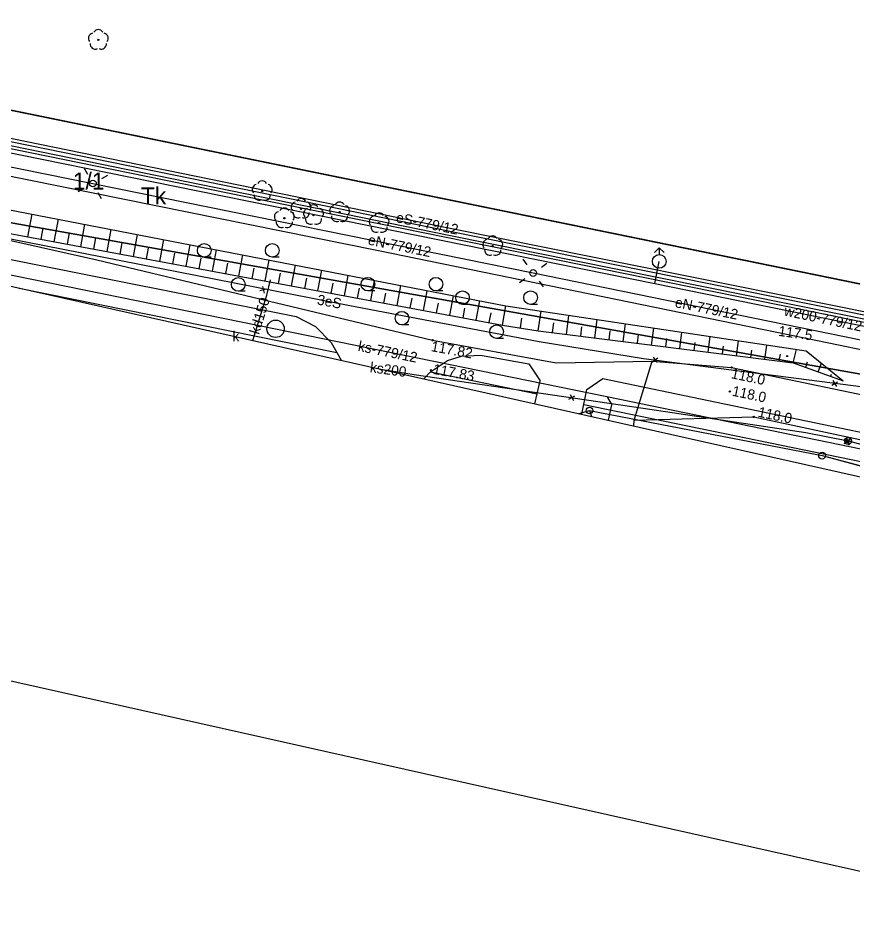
# Model space of a CAD drawing. Extents: x 6424617 to 6425697, y 5665845 to 5667190.
# Drawn here: x 6424720.9 to 6424782.2, y 5665988.5 to 5666054.9 of the extents above; entities that cross this region are included whole.
import ezdxf

# ---------------------------------------------------------------- set-up
doc = ezdxf.new("R2010")
doc.units = 0
for name, color, linetype in [('Warstwa 1', 7, 'Continuous'), ('Warstwa 10', 7, 'Continuous'), ('Warstwa 11', 7, 'Continuous'), ('Warstwa 12', 7, 'Continuous'), ('Warstwa 13', 7, 'Continuous'), ('Warstwa 14', 7, 'Continuous'), ('Warstwa 15', 7, 'Continuous'), ('Warstwa 2', 7, 'Continuous'), ('Warstwa 20', 7, 'Continuous'), ('Warstwa 21', 7, 'Continuous'), ('Warstwa 25', 7, 'Continuous'), ('Warstwa 4', 7, 'Continuous'), ('Warstwa 5', 7, 'Continuous'), ('Warstwa 6', 7, 'Continuous'), ('Warstwa 62', 7, 'Continuous'), ('Warstwa 63', 7, 'Continuous'), ('Warstwa 8', 7, 'Continuous')]:
    doc.layers.add(name, color=color, linetype=linetype)

msp = doc.modelspace()

# ---------------------------------------------------------------- linework, layer by layer
at = {"layer": 'Warstwa 1'}
for p, q in [((6424712.334, 5666049.725), (6424785.747, 5666034.716)), ((6424712.334, 5666049.725), (6424785.747, 5666034.716)), ((6424710.615, 5666041.565), (6424784.211, 5666028.454)), ((6424710.615, 5666041.565), (6424784.211, 5666028.454)), ((6424762.124, 5666025.803), (6424762.89, 5666026.032)), ((6424762.124, 5666025.803), (6424762.89, 5666026.032)), ((6424762.89, 5666026.032), (6424763.044, 5666025.596)), ((6424762.89, 5666026.032), (6424779.981, 5666022.715)), ((6424762.89, 5666026.032), (6424779.981, 5666022.715)), ((6424762.89, 5666026.032), (6424763.044, 5666025.596)), ((6424779.981, 5666022.715), (6424802.225, 5666016.812)), ((6424779.981, 5666022.715), (6424802.225, 5666016.812))]:
    msp.add_line(p, q, dxfattribs=at)
at = {"layer": 'Warstwa 10'}
for p, q in [((6424710.78, 5666042.623), (6424756.735, 5666033.713)), ((6424707.071, 5666041.492), (6424756.504, 5666032.304)), ((6424721.629, 5666038.786), (6424721.94, 5666040.458)), ((6424723.567, 5666038.426), (6424723.875, 5666040.084)), ((6424722.598, 5666038.606), (6424722.753, 5666039.438)), ((6424725.505, 5666038.065), (6424725.81, 5666039.708)), ((6424727.441, 5666037.706), (6424727.744, 5666039.334)), ((6424724.536, 5666038.245), (6424724.69, 5666039.071)), ((6424726.473, 5666037.885), (6424726.625, 5666038.704)), ((6424729.379, 5666037.345), (6424729.679, 5666038.959)), ((6424731.317, 5666036.985), (6424731.614, 5666038.583)), ((6424728.41, 5666037.526), (6424728.561, 5666038.336)), ((6424730.348, 5666037.165), (6424730.497, 5666037.968)), ((6424733.254, 5666036.625), (6424733.548, 5666038.209)), ((6424735.191, 5666036.265), (6424735.483, 5666037.833)), ((6424732.285, 5666036.805), (6424732.433, 5666037.6)), ((6424734.222, 5666036.445), (6424734.369, 5666037.233)), ((6424737.129, 5666035.904), (6424737.418, 5666037.458)), ((6424736.16, 5666036.084), (6424736.306, 5666036.865)), ((6424738.098, 5666035.725), (6424738.241, 5666036.498)), ((6424739.067, 5666035.545), (6424739.352, 5666037.082)), ((6424741.004, 5666035.184), (6424741.287, 5666036.708)), ((6424740.036, 5666035.365), (6424740.177, 5666036.129)), ((6424742.941, 5666034.824), (6424743.222, 5666036.333)), ((6424744.879, 5666034.464), (6424745.157, 5666035.957)), ((6424741.972, 5666035.004), (6424742.114, 5666035.762)), ((6424743.91, 5666034.644), (6424744.05, 5666035.394)), ((6424746.816, 5666034.104), (6424747.091, 5666035.583)), ((6424748.754, 5666033.744), (6424749.025, 5666035.207)), ((6424745.847, 5666034.285), (6424745.986, 5666035.027)), ((6424747.785, 5666033.924), (6424747.922, 5666034.66)), ((6424750.691, 5666033.384), (6424750.961, 5666034.833)), ((6424749.722, 5666033.564), (6424749.857, 5666034.292)), ((6424751.66, 5666033.204), (6424751.794, 5666033.925)), ((6424752.629, 5666033.024), (6424752.895, 5666034.457)), ((6424754.566, 5666032.664), (6424754.83, 5666034.082)), ((6424753.598, 5666032.844), (6424753.731, 5666033.557)), ((6424755.522, 5666032.487), (6424755.663, 5666033.194)), ((6424756.504, 5666032.304), (6424756.735, 5666033.713)), ((6424756.735, 5666033.713), (6424778.815, 5666030.409)), ((6424759.127, 5666031.882), (6424759.332, 5666033.325)), ((6424757.815, 5666032.093), (6424757.924, 5666032.806)), ((6424761.209, 5666031.622), (6424761.383, 5666033.018)), ((6424763.291, 5666031.362), (6424763.459, 5666032.707)), ((6424756.504, 5666032.304), (6424759.127, 5666031.882)), ((6424759.127, 5666031.882), (6424777.865, 5666029.538)), ((6424760.168, 5666031.751), (6424760.263, 5666032.461)), ((6424762.25, 5666031.492), (6424762.335, 5666032.177)), ((6424764.331, 5666031.231), (6424764.414, 5666031.891)), ((6424765.373, 5666031.1), (6424765.535, 5666032.396)), ((6424767.455, 5666030.84), (6424767.611, 5666032.085)), ((6424766.414, 5666030.97), (6424766.494, 5666031.606)), ((6424768.495, 5666030.711), (6424768.572, 5666031.32)), ((6424769.537, 5666030.58), (6424769.686, 5666031.775)), ((6424771.619, 5666030.32), (6424771.762, 5666031.464)), ((6424773.701, 5666030.059), (6424773.838, 5666031.153)), ((6424770.578, 5666030.449), (6424770.651, 5666031.035)), ((6424772.659, 5666030.189), (6424772.73, 5666030.749)), ((6424775.783, 5666029.798), (6424775.913, 5666030.843)), ((6424777.865, 5666029.538), (6424778.1, 5666030.515)), ((6424774.742, 5666029.929), (6424774.808, 5666030.463)), ((6424776.823, 5666029.668), (6424776.915, 5666030.174)), ((6424778.815, 5666030.409), (6424781.537, 5666028.2)), ((6424777.865, 5666029.538), (6424781.537, 5666028.2)), ((6424778.783, 5666029.204), (6424778.899, 5666029.607)), ((6424779.701, 5666028.869), (6424779.931, 5666029.503)), ((6424780.619, 5666028.534), (6424780.677, 5666028.693))]:
    msp.add_line(p, q, dxfattribs=at)
msp.add_lwpolyline([(6424656.071, 5666052.546), (6424661.157, 5666051.396), (6424669.018, 5666049.655), (6424675.606, 5666048.248), (6424687.507, 5666045.627), (6424688.596, 5666045.389), (6424711.614, 5666040.344), (6424745.27, 5666033.742), (6424759.201, 5666031.098), (6424766.854, 5666029.843), (6424786.263, 5666027.358), (6424788.423, 5666027.048), (6424792.547, 5666026.577), (6424800.463, 5666024.133), (6424809.296, 5666021.315), (6424821.58, 5666017.547), (6424829.542, 5666015.101), (6424836.576, 5666013.009), (6424850.417, 5666008.804), (6424857.534, 5666006.674), (6424862.301, 5666005.107)], dxfattribs=at)
for centre in [(6424762.89, 5666026.032), (6424779.981, 5666022.715)]:
    msp.add_circle(centre, 0.25, dxfattribs=at)
at = {"layer": 'Warstwa 11'}
for centre in [(6424726.8, 5666053.26), (6424738.84, 5666042.15), (6424741.7, 5666040.85), (6424742.61, 5666040.39), (6424744.53, 5666040.59), (6424740.47, 5666040.15), (6424747.43, 5666039.8), (6424755.78, 5666038.11)]:
    msp.add_circle(centre, 0.05, dxfattribs=at)
for centre, start, end in [((6424726.443, 5666053.376), 102.14713, 221.85287), ((6424726.8, 5666053.635), 30.14713, 149.85287), ((6424727.157, 5666053.376), 318.14713, 77.85287), ((6424726.58, 5666052.957), 174.14713, 293.85287), ((6424727.02, 5666052.957), 246.14713, 5.85287), ((6424738.483, 5666042.266), 102.14713, 221.85287), ((6424738.84, 5666042.525), 30.14713, 149.85287), ((6424739.197, 5666042.266), 318.14713, 77.85287), ((6424738.62, 5666041.847), 174.14713, 293.85287), ((6424739.06, 5666041.847), 246.14713, 5.85287), ((6424741.343, 5666040.966), 102.14713, 221.85287), ((6424741.7, 5666041.225), 30.14713, 149.85287), ((6424742.057, 5666040.966), 318.14713, 77.85287), ((6424742.61, 5666040.765), 30.14713, 149.85287), ((6424744.53, 5666040.965), 30.14713, 149.85287), ((6424740.113, 5666040.266), 102.14713, 221.85287), ((6424740.47, 5666040.525), 30.14713, 149.85287), ((6424740.827, 5666040.266), 318.14713, 77.85287), ((6424741.48, 5666040.547), 174.14713, 293.85287), ((6424741.92, 5666040.547), 246.14713, 5.85287), ((6424742.253, 5666040.506), 102.14713, 221.85287), ((6424742.967, 5666040.506), 318.14713, 77.85287), ((6424744.173, 5666040.706), 102.14713, 221.85287), ((6424744.887, 5666040.706), 318.14713, 77.85287), ((6424747.43, 5666040.175), 30.14713, 149.85287), ((6424740.25, 5666039.847), 174.14713, 293.85287), ((6424740.69, 5666039.847), 246.14713, 5.85287), ((6424742.39, 5666040.087), 174.14713, 293.85287), ((6424742.83, 5666040.087), 246.14713, 5.85287), ((6424744.31, 5666040.287), 174.14713, 293.85287), ((6424744.75, 5666040.287), 246.14713, 5.85287), ((6424747.073, 5666039.916), 102.14713, 221.85287), ((6424747.787, 5666039.916), 318.14713, 77.85287), ((6424747.21, 5666039.497), 174.14713, 293.85287), ((6424747.65, 5666039.497), 246.14713, 5.85287), ((6424755.423, 5666038.226), 102.14713, 221.85287), ((6424755.78, 5666038.485), 30.14713, 149.85287), ((6424756.137, 5666038.226), 318.14713, 77.85287), ((6424755.56, 5666037.807), 174.14713, 293.85287), ((6424756, 5666037.807), 246.14713, 5.85287)]:
    msp.add_arc(centre, 0.375, start, end, dxfattribs=at)
at = {"layer": 'Warstwa 12'}
for points in [[(6424738.156, 5666031.176), (6424739.178, 5666034.503), (6424739.443, 5666035.64)], [(6424747.564, 5666029.067), (6424750.011, 5666028.68), (6424766.827, 5666026.199), (6424778.788, 5666024.413), (6424781.89, 5666023.794), (6424800.356, 5666018.883), (6424811.076, 5666016.019), (6424822.07, 5666013.113), (6424829.403, 5666010.718)]]:
    msp.add_lwpolyline(points, dxfattribs=at)
at = {"layer": 'Warstwa 13'}
for centre in [(6424777.418, 5666030.032), (6424773.33, 5666029.19), (6424773.2, 5666027.42), (6424774.96, 5666025.56)]:
    msp.add_circle(centre, 0.045, dxfattribs=at)
at = {"layer": 'Warstwa 14'}
msp.add_circle((6424781.89, 5666023.794), 0.045, dxfattribs=at)
at = {"layer": 'Warstwa 20'}
for p, q in [((6424707.071, 5666041.492), (6424756.504, 5666032.304)), ((6424756.504, 5666032.304), (6424759.127, 5666031.882)), ((6424759.127, 5666031.882), (6424777.865, 5666029.538)), ((6424777.865, 5666029.538), (6424781.537, 5666028.2))]:
    msp.add_line(p, q, dxfattribs=at)
at = {"layer": 'Warstwa 21'}
for p, q in [((6424710.78, 5666042.623), (6424756.735, 5666033.713)), ((6424756.735, 5666033.713), (6424778.815, 5666030.409)), ((6424778.815, 5666030.409), (6424781.537, 5666028.2))]:
    msp.add_line(p, q, dxfattribs=at)
at = {"layer": 'Warstwa 25'}
for centre in [(6424751.36, 5666031.19), (6424751.23, 5666028.99)]:
    msp.add_circle(centre, 0.045, dxfattribs=at)
at = {"layer": 'Warstwa 4'}
msp.add_circle((6424781.89, 5666023.794), 0.25, dxfattribs=at)
at = {"layer": 'Warstwa 6'}
for p, q in [((6424735.08, 5666037.293), (6424734.58, 5666037.293)), ((6424740.08, 5666037.293), (6424739.58, 5666037.293)), ((6424737.58, 5666034.793), (6424737.08, 5666034.793)), ((6424747.11, 5666034.813), (6424746.61, 5666034.813)), ((6424752.11, 5666034.813), (6424751.61, 5666034.813)), ((6424754.06, 5666033.823), (6424753.56, 5666033.823)), ((6424759.06, 5666033.823), (6424758.56, 5666033.823)), ((6424749.61, 5666032.313), (6424749.11, 5666032.313)), ((6424756.56, 5666031.323), (6424756.06, 5666031.323))]:
    msp.add_line(p, q, dxfattribs=at)
for points in [[(6424658.972, 5666088.288), (6424687.905, 5666078.903), (6424716.673, 5666070.324), (6424715.697, 5666065.716), (6424712.334, 5666049.725), (6424785.747, 5666034.716), (6424788.428, 5666045.534), (6424790.341, 5666053.242), (6424828.327, 5666041.072), (6424860.534, 5666028.943), (6424934.12, 5666007.202), (6424963.728, 5665998.454), (6425016.619, 5665983.165), (6425073.513, 5665966.428), (6425123.829, 5665952.421), (6425122.41, 5665946.75), (6425151.645, 5665938.47)], [(6425042.513, 5665962.938), (6424959.921, 5665983.009), (6424856.845, 5666006.746), (6424825.409, 5666018.086), (6424784.685, 5666030.409), (6424784.211, 5666028.454), (6424710.615, 5666041.565), (6424651.301, 5666054.074)], [(6424762.124, 5666025.803), (6424762.89, 5666026.032), (6424779.981, 5666022.715), (6424802.205, 5666016.816)], [(6424762.124, 5666025.803), (6424762.89, 5666026.032), (6424779.981, 5666022.715), (6424802.205, 5666016.816)]]:
    msp.add_lwpolyline(points, dxfattribs=at)
msp.add_lwpolyline([(6424784.211, 5666028.454), (6424784.685, 5666030.409), (6424785.747, 5666034.716), (6424712.334, 5666049.725), (6424710.615, 5666041.565)], close=True, dxfattribs=at)
for centre in [(6424734.58, 5666037.793), (6424739.58, 5666037.793), (6424737.08, 5666035.293), (6424746.61, 5666035.313), (6424751.61, 5666035.313), (6424753.56, 5666034.323), (6424758.56, 5666034.323), (6424749.11, 5666032.813), (6424756.06, 5666031.823)]:
    msp.add_circle(centre, 0.5, dxfattribs=at)
at = {"layer": 'Warstwa 62'}
for p, q in [((6424680.519, 5666053.078), (6424730.737, 5666042.85)), ((6424693.626, 5666051.26), (6424752.619, 5666039.206)), ((6424693.672, 5666051.482), (6424752.664, 5666039.429)), ((6424693.566, 5666050.967), (6424752.56, 5666038.913)), ((6424695.08, 5666049.072), (6424726.402, 5666042.708)), ((6424696.215, 5666048.15), (6424747.267, 5666037.798)), ((6424717.93, 5666045.774), (6424737.641, 5666041.751)), ((6424686.027, 5666042.978), (6424739.83, 5666032.032)), ((6424726.402, 5666042.708), (6424758.753, 5666036.132)), ((6424730.737, 5666042.85), (6424767.696, 5666035.369)), ((6424737.641, 5666041.751), (6424778.553, 5666033.455)), ((6424752.619, 5666039.206), (6424794.453, 5666030.768)), ((6424752.664, 5666039.429), (6424794.498, 5666030.991)), ((6424752.56, 5666038.913), (6424794.394, 5666030.476)), ((6424747.267, 5666037.798), (6424780.485, 5666030.991)), ((6424768.015, 5666037.982), (6424767.661, 5666037.628)), ((6424768.015, 5666037.982), (6424768.015, 5666037.482)), ((6424768.015, 5666037.982), (6424768.369, 5666037.628)), ((6424718.231, 5666037.55), (6424741.346, 5666032.941)), ((6424767.696, 5666035.369), (6424768.015, 5666036.982)), ((6424758.753, 5666036.132), (6424790.057, 5666029.751)), ((6424767.696, 5666035.369), (6424788.557, 5666031.094)), ((6424720.992, 5666035.025), (6424744.315, 5666030.294)), ((6424778.553, 5666033.455), (6424811.027, 5666026.754)), ((6424741.346, 5666032.941), (6424742.764, 5666032.196)), ((6424739.83, 5666032.032), (6424764.168, 5666027.06)), ((6424742.764, 5666032.196), (6424743.899, 5666031.026)), ((6424743.899, 5666031.026), (6424744.639, 5666029.723)), ((6424780.485, 5666030.991), (6424817.037, 5666023.581)), ((6424752.469, 5666029.715), (6424753.48, 5666030.016)), ((6424753.48, 5666030.016), (6424754.88, 5666030.105)), ((6424754.88, 5666030.105), (6424758.425, 5666029.449)), ((6424751.211, 5666028.881), (6424752.469, 5666029.715)), ((6424758.425, 5666029.449), (6424759.258, 5666028.208)), ((6424750.719, 5666028.36), (6424751.211, 5666028.881)), ((6424751.211, 5666028.881), (6424759.046, 5666027.268)), ((6424759.046, 5666027.268), (6424759.258, 5666028.208)), ((6424762.697, 5666027.57), (6424763.867, 5666028.385)), ((6424763.867, 5666028.385), (6424781.877, 5666024.627)), ((6424758.879, 5666026.53), (6424759.046, 5666027.268)), ((6424762.321, 5666025.758), (6424762.697, 5666027.57)), ((6424764.168, 5666027.06), (6424764.541, 5666026.44)), ((6424764.168, 5666027.06), (6424783.667, 5666023.036)), ((6424762.479, 5666026.467), (6424823.652, 5666013.912)), ((6424764.296, 5666025.316), (6424764.541, 5666026.44)), ((6424781.877, 5666024.627), (6424805.453, 5666019.77))]:
    msp.add_line(p, q, dxfattribs=at)
for points in [[(6424726.039, 5666043.364), (6424725.796, 5666043.802)], [(6424727.058, 5666043.072), (6424727.496, 5666043.315)], [(6424725.747, 5666042.345), (6424725.309, 5666042.102)], [(6424726.766, 5666042.053), (6424727.009, 5666041.615)], [(6424758.315, 5666036.74), (6424758.023, 5666037.147)], [(6424759.361, 5666036.57), (6424759.768, 5666036.862)], [(6424738.852, 5666035.145), (6424738.983, 5666034.662)], [(6424758.144, 5666035.694), (6424757.738, 5666035.402)], [(6424759.19, 5666035.523), (6424759.482, 5666035.117)], [(6424738.676, 5666034.838), (6424739.159, 5666034.97)], [(6424767.515, 5666029.602), (6424767.912, 5666029.907)], [(6424767.562, 5666029.953), (6424767.866, 5666029.556)], [(6424780.689, 5666027.885), (6424781.115, 5666028.149)], [(6424780.77, 5666028.23), (6424781.034, 5666027.805)], [(6424761.468, 5666027.199), (6424761.71, 5666026.761)], [(6424761.37, 5666026.859), (6424761.808, 5666027.102)], [(6424781.639, 5666023.715), (6424782.079, 5666023.953)], [(6424781.73, 5666023.947), (6424781.935, 5666023.49)], [(6424781.74, 5666024.054), (6424781.978, 5666023.614)], [(6424781.604, 5666023.616), (6424782.061, 5666023.821)]]:
    msp.add_lwpolyline(points, dxfattribs=at)
for centre, radius in [((6424726.402, 5666042.708), 0.25), ((6424768.015, 5666036.982), 0.5), ((6424758.753, 5666036.132), 0.25), ((6424739.83, 5666032.032), 0.638)]:
    msp.add_circle(centre, radius, dxfattribs=at)
at = {"layer": 'Warstwa 63'}
for points in [[(6424616.753, 5666029.383), (6424876.877, 5667189.58), (6425697.302, 5667005.636), (6425437.178, 5665845.439)], [(6425341.164, 5665895.978), (6425588.9, 5667000.928), (6424898.307, 5667155.763), (6424650.57, 5666050.814)]]:
    msp.add_lwpolyline(points, close=True, dxfattribs=at)
at = {"layer": 'Warstwa 8'}
for p, q in [((6424701.48, 5666042.74), (6424726.7, 5666037.11)), ((6424726.7, 5666037.11), (6424751.36, 5666031.19)), ((6424751.36, 5666031.19), (6424760.45, 5666029.53)), ((6424760.45, 5666029.53), (6424767.49, 5666029.66)), ((6424766.17, 5666025.31), (6424767.49, 5666029.66)), ((6424766.17, 5666025.31), (6424767.49, 5666029.66)), ((6424767.49, 5666029.66), (6424773.33, 5666029.19)), ((6424773.33, 5666029.19), (6424797.6, 5666024.11)), ((6424766.151, 5666024.9), (6424766.17, 5666025.31)), ((6424766.17, 5666025.31), (6424774.96, 5666025.56)), ((6424774.96, 5666025.56), (6424796.47, 5666020.98))]:
    msp.add_line(p, q, dxfattribs=at)

# ---------------------------------------------------------------- texts
at = {"layer": 'Warstwa 11'}
msp.add_text('3eS', height=0.75, rotation=349.59593, dxfattribs=at).set_placement((6424742.835, 5666033.826))
at = {"layer": 'Warstwa 13'}
for s, rotation, p in [('kd150', 72.86877, (6424738.602, 5666031.572)), ('117.5', 352.17997, (6424776.733, 5666031.52)), ('ks200', 352.30029, (6424746.727, 5666028.851)), ('118.0', 348.18072, (6424773.249, 5666028.41)), ('118.0', 348.18072, (6424773.327, 5666027.125)), ('118.0', 347.98019, (6424775.226, 5666025.583))]:
    msp.add_text(s, height=0.75, rotation=rotation, dxfattribs=at).set_placement(p)
at = {"layer": 'Warstwa 15'}
msp.add_text('1/1', height=1.25, dxfattribs=at).set_placement((6424724.928, 5666042.259))
at = {"layer": 'Warstwa 2'}
msp.add_text('Tk', height=1.25, dxfattribs=at).set_placement((6424729.935, 5666041.178))
at = {"layer": 'Warstwa 25'}
for s, p in [('117.82', (6424751.208, 5666030.399)), ('117.83', (6424751.344, 5666028.73))]:
    msp.add_text(s, height=0.75, rotation=349.65322, dxfattribs=at).set_placement(p)
at = {"layer": 'Warstwa 5'}
msp.add_text('k', height=0.75, dxfattribs=at).set_placement((6424736.66, 5666031.108))
at = {"layer": 'Warstwa 62'}
for s, height, rotation, p in [('eS-779/12', 0.75, 348.45189, (6424748.63, 5666039.87)), ('eN-779/12', 0.75, 348.50906, (6424746.57, 5666038.226)), ('eN-779/12', 0.75, 348.47809, (6424769.126, 5666033.635)), ('w200-779/12', 0.74999, 348.22743, (6424777.149, 5666033.016)), ('ks-779/12', 0.75, 348.45353, (6424745.838, 5666030.422))]:
    msp.add_text(s, height=height, rotation=rotation, dxfattribs=at).set_placement(p)

doc.saveas('drawing.dxf')
